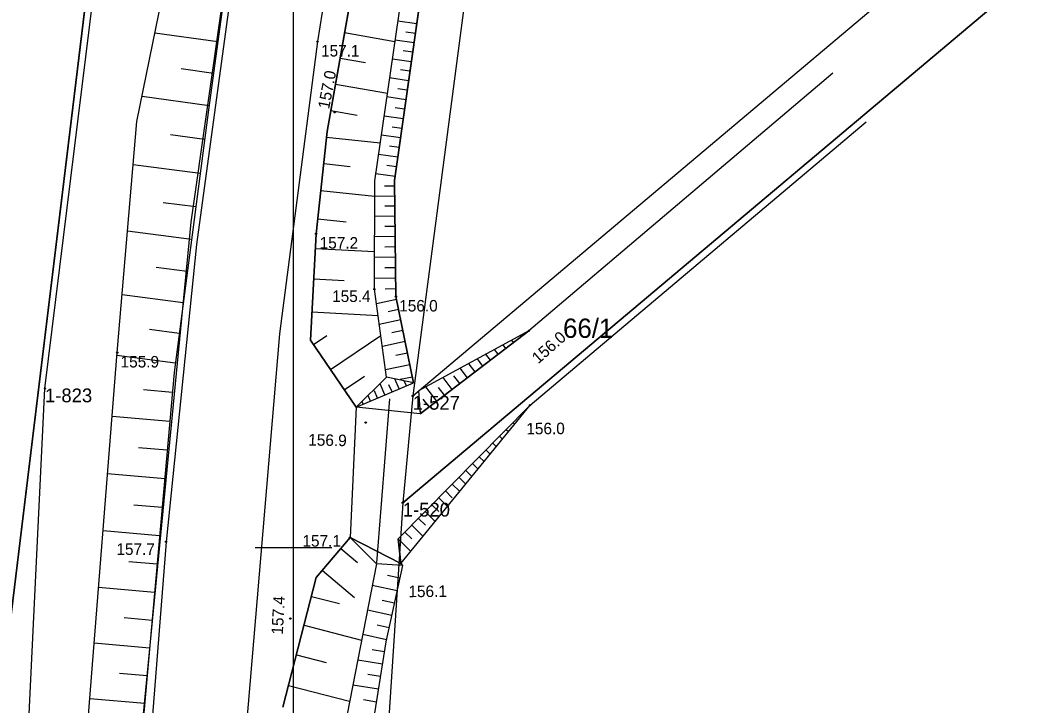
# Model space of a CAD drawing. Extents: x 5598798 to 5599616, y 5661498 to 5662453.
# Drawn here: x 5599182.2 to 5599247.3, y 5661939.7 to 5661984.4 of the extents above; entities that cross this region are included whole.
import ezdxf

# ---------------------------------------------------------------- set-up
doc = ezdxf.new("R2010")
doc.units = 0
for name, color, linetype in [('BUBZ_L_1', 7, 'Continuous'), ('BUIB_L_4', 7, 'Continuous'), ('Dzialki', 7, 'Continuous'), ('Kontury', 7, 'Continuous'), ('KTJZ_L_0', 7, 'Continuous'), ('Numery_dzialek', 7, 'Continuous'), ('Numery_punktow', 7, 'Continuous'), ('Podzial_sekcyjny_krzyze', 7, 'Continuous'), ('Podzial_sekcyjny_podstawowy', 7, 'Continuous'), ('PTRW_L_0', 7, 'Continuous'), ('Punkty', 7, 'Continuous'), ('RTPW_T_0', 7, 'Continuous'), ('SUPT_L_0', 7, 'Continuous'), ('SUPW_L_0', 7, 'Continuous'), ('Uzytki', 7, 'Continuous')]:
    doc.layers.add(name, color=color, linetype=linetype)

# ---------------------------------------------------------------- blocks, each defined once
blk = doc.blocks.new('GRO')
blk.add_circle((0, 0), 0.045)
blk = doc.blocks.new('POINT_DISPLAY')
blk.add_line((0, 0), (0, 0))
blk = doc.blocks.new('2_RTPW01')
blk.add_circle((0, 0), 0.045)

msp = doc.modelspace()

# ---------------------------------------------------------------- linework, layer by layer
at = {"layer": 'BUBZ_L_1'}
for p, q in [((5599189.8, 5661977.78), (5599196.49, 5662010.61)), ((5599198.63, 5662008.86), (5599194.46, 5661978.54)), ((5599205.3, 5661973.9), (5599209.49, 5662002.77)), ((5599206.61, 5662002.2), (5599202.2, 5661977.13)), ((5599210.61, 5662002.29), (5599206.59, 5661973.92)), ((5599208.037029, 5661984.131993), (5599206.810233, 5661984.305829)), ((5599203.333533, 5661983.573915), (5599206.620102, 5661982.995783)), ((5599207.950111, 5661983.518595), (5599207.335681, 5661983.605659)), ((5599195.067793, 5661982.959252), (5599190.970251, 5661983.522799)), ((5599207.863047, 5661982.904165), (5599206.632119, 5661983.078586)), ((5599207.775836, 5661982.288701), (5599207.159337, 5661982.376059)), ((5599203.040063, 5661981.905599), (5599204.708379, 5661981.61213)), ((5599207.688479, 5661981.672202), (5599206.453405, 5661981.84721)), ((5599194.786019, 5661980.910481), (5599192.671239, 5661981.201333)), ((5599207.600975, 5661981.054665), (5599206.982399, 5661981.142316)), ((5599207.513323, 5661980.436089), (5599206.27409, 5661980.611687)), ((5599202.742124, 5661980.21187), (5599206.129581, 5661979.615991)), ((5599207.425524, 5661979.816472), (5599206.804865, 5661979.904419)), ((5599194.495167, 5661978.7957), (5599190.129333, 5661979.396146)), ((5599207.337577, 5661979.195813), (5599206.09417, 5661979.372002)), ((5599194.46, 5661978.54), (5599192.22, 5661961.41)), ((5599202.439646, 5661978.492342), (5599204.159174, 5661978.189864)), ((5599207.249483, 5661978.574109), (5599206.626733, 5661978.662352)), ((5599188.51, 5661962.71), (5599189.8, 5661977.78)), ((5599207.16124, 5661977.95136), (5599205.913645, 5661978.128143)), ((5599202.2, 5661977.13), (5599201.48, 5661970.46)), ((5599207.072848, 5661977.327562), (5599206.448001, 5661977.416102)), ((5599194.207763, 5661976.611064), (5599191.978801, 5661976.902533)), ((5599202.159549, 5661976.755264), (5599205.659561, 5661976.377451)), ((5599206.984308, 5661976.702715), (5599205.732511, 5661976.880093)), ((5599206.895619, 5661976.076817), (5599206.268667, 5661976.165655)), ((5599206.80678, 5661975.449865), (5599205.550767, 5661975.627841)), ((5599193.916293, 5661974.382101), (5599189.557924, 5661974.952022)), ((5599201.974039, 5661975.036719), (5599203.692584, 5661974.851209)), ((5599206.717792, 5661974.821859), (5599206.088729, 5661974.910996)), ((5599205.28, 5661966.84), (5599205.3, 5661973.9)), ((5599206.628655, 5661974.192795), (5599205.368412, 5661974.371371)), ((5599206.59, 5661973.92), (5599206.68, 5661966.36)), ((5599201.784446, 5661973.280357), (5599205.29717, 5661972.901172)), ((5599206.594296, 5661973.55913), (5599205.946643, 5661973.55142)), ((5599206.602006, 5661972.911477), (5599205.297156, 5661972.895943)), ((5599193.631333, 5661972.202916), (5599191.500814, 5661972.481513)), ((5599206.609773, 5661972.259052), (5599205.95254, 5661972.251228)), ((5599201.58434, 5661971.426597), (5599203.4381, 5661971.226491)), ((5599206.617597, 5661971.601819), (5599205.293445, 5661971.586055)), ((5599193.352736, 5661970.072397), (5599189.186856, 5661970.617147)), ((5599206.625479, 5661970.939743), (5599205.958524, 5661970.931803)), ((5599201.48, 5661970.46), (5599201.11, 5661963.53)), ((5599206.633419, 5661970.272788), (5599205.289679, 5661970.256791)), ((5599201.428839, 5661969.501771), (5599205.286957, 5661969.295782)), ((5599206.641418, 5661969.600918), (5599205.964597, 5661969.59286)), ((5599206.649475, 5661968.924097), (5599205.285858, 5661968.907863)), ((5599193.080361, 5661967.989457), (5599191.043937, 5661968.25575)), ((5599206.657592, 5661968.242288), (5599205.970759, 5661968.234112)), ((5599201.323174, 5661967.52269), (5599203.302255, 5661967.417025)), ((5599206.665768, 5661967.555455), (5599205.28198, 5661967.538982)), ((5599206.08, 5661961.11), (5599205.28, 5661966.84)), ((5599206.674005, 5661966.863561), (5599205.977012, 5661966.855264)), ((5599192.814069, 5661965.953034), (5599188.832177, 5661966.473725)), ((5599206.719171, 5661966.170562), (5599205.411223, 5661965.900113)), ((5599206.68, 5661966.36), (5599207.84, 5661960.75)), ((5599201.208129, 5661965.36793), (5599205.517649, 5661965.137841)), ((5599206.854395, 5661965.516588), (5599206.179078, 5661965.376951)), ((5599206.994033, 5661964.841271), (5599205.599319, 5661964.552881)), ((5599192.553723, 5661963.962088), (5599190.607239, 5661964.216619)), ((5599207.138228, 5661964.143914), (5599206.418112, 5661963.995013)), ((5599215.350881, 5661964.125085), (5599208.146474, 5661960.209571)), ((5599208.270337, 5661958.721684), (5599215.350881, 5661964.125085)), ((5599201.11, 5661963.53), (5599204.09, 5661959.15)), ((5599201.308213, 5661963.238667), (5599202.171743, 5661963.826183)), ((5599202.423064, 5661961.60006), (5599205.700278, 5661963.829762)), ((5599207.287129, 5661963.423797), (5599205.799892, 5661963.116276)), ((5599214.350857, 5661963.361933), (5599214.232375, 5661963.51719)), ((5599214.850869, 5661963.743509), (5599214.791628, 5661963.821138)), ((5599213.350832, 5661962.598781), (5599213.113869, 5661962.909294)), ((5599213.850844, 5661962.980357), (5599213.673122, 5661963.213242)), ((5599186.4, 5661936.1), (5599188.51, 5661962.71)), ((5599192.299192, 5661962.015604), (5599188.49439, 5661962.513138)), ((5599207.44089, 5661962.680178), (5599206.673002, 5661962.521399)), ((5599212.350808, 5661961.835628), (5599211.995363, 5661962.301399)), ((5599212.85082, 5661962.217204), (5599212.554616, 5661962.605347)), ((5599207.599669, 5661961.91229), (5599206.013771, 5661961.584368)), ((5599211.350783, 5661961.072476), (5599210.876856, 5661961.693503)), ((5599211.850795, 5661961.454052), (5599211.469219, 5661961.954064)), ((5599192.22, 5661961.41), (5599190.05, 5661936.96)), ((5599203.317148, 5661960.285936), (5599204.631272, 5661961.180021)), ((5599204.09, 5661959.15), (5599206.08, 5661961.11)), ((5599207.84, 5661960.75), (5599206.08, 5661961.11)), ((5599206.900159, 5661960.349001), (5599206.622842, 5661960.998964)), ((5599207.76363, 5661961.119341), (5599206.955405, 5661960.952222)), ((5599207.37008, 5661960.549501), (5599207.231421, 5661960.874482)), ((5599210.350759, 5661960.309324), (5599209.75835, 5661961.085608)), ((5599210.850771, 5661960.6909), (5599210.469195, 5661961.190912)), ((5599192.104381, 5661960.107284), (5599190.217282, 5661960.274768)), ((5599204.09, 5661959.15), (5599207.84, 5661960.75)), ((5599205.490399, 5661959.747503), (5599205.289899, 5661960.217424)), ((5599205.960319, 5661959.948003), (5599205.646644, 5661960.683177)), ((5599206.430239, 5661960.148502), (5599206.22974, 5661960.618422)), ((5599208.146474, 5661960.209571), (5599208.270337, 5661958.721684)), ((5599209.350734, 5661959.546171), (5599208.639844, 5661960.477712)), ((5599209.850746, 5661959.927747), (5599209.46917, 5661960.42776)), ((5599204.550558, 5661959.346505), (5599204.473317, 5661959.527538)), ((5599205.020478, 5661959.547004), (5599204.864426, 5661959.912751)), ((5599208.850722, 5661959.164595), (5599208.469146, 5661959.664607)), ((5599215.430897, 5661959.284622), (5599206.834986, 5661950.565233)), ((5599207.011575, 5661948.958488), (5599215.430897, 5661959.284622)), ((5599208.35071, 5661958.783019), (5599208.254765, 5661958.908744)), ((5599215.196893, 5661959.047257), (5599215.21933, 5661959.025139)), ((5599191.936896, 5661958.220185), (5599188.180423, 5661958.553581)), ((5599214.756793, 5661958.600835), (5599214.821426, 5661958.537117)), ((5599213.876592, 5661957.70799), (5599214.025618, 5661957.561075)), ((5599214.316693, 5661958.154412), (5599214.423522, 5661958.049096)), ((5599213.436492, 5661957.261568), (5599213.627714, 5661957.073053)), ((5599191.770197, 5661956.341948), (5599189.900782, 5661956.507864)), ((5599212.556291, 5661956.368723), (5599212.831907, 5661956.097011)), ((5599212.996391, 5661956.815145), (5599213.22981, 5661956.585032)), ((5599212.116191, 5661955.922301), (5599212.434003, 5661955.60899)), ((5599211.23599, 5661955.029456), (5599211.638195, 5661954.632947)), ((5599211.67609, 5661955.475879), (5599212.036099, 5661955.120968)), ((5599191.604282, 5661954.472533), (5599187.883011, 5661954.802805)), ((5599210.79589, 5661954.583034), (5599211.240291, 5661954.144926)), ((5599209.915689, 5661953.690189), (5599210.362111, 5661953.250089)), ((5599210.355789, 5661954.136612), (5599210.842387, 5661953.656904)), ((5599209.475588, 5661953.243767), (5599210.04658, 5661952.680862)), ((5599191.439146, 5661952.611897), (5599189.587249, 5661952.776258)), ((5599208.595388, 5661952.350922), (5599209.250772, 5661951.704819)), ((5599209.035488, 5661952.797345), (5599209.48191, 5661952.357244)), ((5599208.155287, 5661951.9045), (5599208.60171, 5661951.4644)), ((5599191.274785, 5661950.76), (5599187.588386, 5661951.087178)), ((5599207.715187, 5661951.458078), (5599208.454964, 5661950.728777)), ((5599201.49, 5661948.04), (5599203.69, 5661950.65)), ((5599203.69, 5661950.65), (5599205.42, 5661948.94)), ((5599206.834986, 5661950.565233), (5599207.011575, 5661948.958488)), ((5599206.834986, 5661950.565233), (5599207.659157, 5661949.752734)), ((5599207.275086, 5661951.011655), (5599207.721509, 5661950.571555)), ((5599203.096379, 5661949.945749), (5599204.178034, 5661949.034009)), ((5599191.111197, 5661948.916801), (5599189.276653, 5661949.079621)), ((5599201.891058, 5661948.515801), (5599203.981475, 5661946.753763)), ((5599205.42, 5661948.94), (5599203.24, 5661937.82)), ((5599207.13, 5661948.83), (5599205.42, 5661948.94)), ((5599206.04, 5661943.86), (5599207.13, 5661948.83)), ((5599199.31, 5661939.6), (5599201.49, 5661948.04)), ((5599206.948566, 5661948.002729), (5599206.127704, 5661948.182757)), ((5599190.948376, 5661947.082257), (5599187.296522, 5661947.406369)), ((5599206.768538, 5661947.181866), (5599205.145129, 5661947.537906)), ((5599201.174892, 5661946.820039), (5599202.99736, 5661946.349307)), ((5599206.590518, 5661946.370162), (5599205.78787, 5661946.546195)), ((5599206.414485, 5661945.567513), (5599204.827097, 5661945.915652)), ((5599190.786321, 5661945.25633), (5599188.968969, 5661945.417625)), ((5599200.689788, 5661944.941931), (5599204.446003, 5661943.971724)), ((5599206.240415, 5661944.773819), (5599205.455576, 5661944.945947)), ((5599206.068288, 5661943.988981), (5599204.516122, 5661944.329395)), ((5599190.625026, 5661943.438978), (5599187.007393, 5661943.760052)), ((5599205.05, 5661937.6), (5599206.04, 5661943.86)), ((5599205.936517, 5661943.20565), (5599205.140837, 5661943.331485)), ((5599200.189874, 5661943.006485), (5599202.12532, 5661942.506572)), ((5599205.810682, 5661942.409971), (5599204.190077, 5661942.666265)), ((5599190.464489, 5661941.630162), (5599188.664167, 5661941.789945)), ((5599205.682535, 5661941.599668), (5599204.857341, 5661941.73017)), ((5599199.674698, 5661941.011951), (5599203.663767, 5661939.981599)), ((5599205.552033, 5661940.774474), (5599203.871313, 5661941.040275)), ((5599190.304706, 5661939.82984), (5599186.720973, 5661940.147905)), ((5599205.419133, 5661939.934114), (5599204.563328, 5661940.069456))]:
    msp.add_line(p, q, dxfattribs=at)
at = {"layer": 'BUIB_L_4'}
msp.add_line((5599205.439605, 5661949.012802), (5599206.277475, 5661959.686865), dxfattribs=at)
at = {"layer": 'Dzialki'}
for p, q in [((5599207.78, 5661959.89), (5599289.91, 5662029.05)), ((5599207.13, 5661952.92), (5599291.05, 5662023.52)), ((5599212.74, 5661997.6), (5599207.78, 5661959.89)), ((5599183.8, 5661960.37), (5599187.02, 5661986.57)), ((5599182.1, 5661925.2), (5599183.8, 5661960.37)), ((5599207.78, 5661959.89), (5599207.13, 5661952.92)), ((5599207.13, 5661952.92), (5599202.8, 5661886.51))]:
    msp.add_line(p, q, dxfattribs=at)
at = {"layer": 'Kontury'}
for p, q in [((5599207.78, 5661959.89), (5599289.91, 5662029.05)), ((5599291.05, 5662023.52), (5599207.13, 5661952.92)), ((5599212.74, 5661997.6), (5599207.78, 5661959.89)), ((5599183.8, 5661960.37), (5599187.02, 5661986.57)), ((5599182.1, 5661925.2), (5599183.8, 5661960.37)), ((5599207.13, 5661952.92), (5599202.8, 5661886.51))]:
    msp.add_line(p, q, dxfattribs=at)
at = {"layer": 'KTJZ_L_0'}
for p, q in [((5599204.57, 5662002.13), (5599201.57, 5661982.98)), ((5599202.2, 5661977.13), (5599206.61, 5662002.2)), ((5599196.27, 5661988.82), (5599193.67, 5661969.75)), ((5599201.57, 5661982.98), (5599199.1, 5661963.93)), ((5599235.17, 5661980.92), (5599215.35, 5661964.13)), ((5599215.43, 5661959.28), (5599237.35, 5661977.76)), ((5599201.48, 5661970.46), (5599202.2, 5661977.13)), ((5599201.11, 5661963.53), (5599201.48, 5661970.46)), ((5599193.67, 5661969.75), (5599191.7, 5661950.38)), ((5599215.35, 5661964.13), (5599208.27, 5661958.72)), ((5599199.1, 5661963.93), (5599196.72, 5661936.01)), ((5599204.09, 5661959.15), (5599201.11, 5661963.53)), ((5599204.09, 5661959.15), (5599203.69, 5661950.65)), ((5599208.27, 5661958.72), (5599204.09, 5661959.15)), ((5599206.83, 5661950.57), (5599215.43, 5661959.28)), ((5599191.7, 5661950.38), (5599190.16, 5661930.69)), ((5599201.49, 5661948.04), (5599203.69, 5661950.65)), ((5599203.69, 5661950.65), (5599207.01, 5661948.96)), ((5599207.01, 5661948.96), (5599206.83, 5661950.57)), ((5599199.31, 5661939.6), (5599201.49, 5661948.04))]:
    msp.add_line(p, q, dxfattribs=at)
at = {"layer": 'Podzial_sekcyjny_krzyze'}
for p, q in [((5599200, 5661947.5), (5599200, 5661952.5)), ((5599197.5, 5661950), (5599202.5, 5661950))]:
    msp.add_line(p, q, dxfattribs=at)
at = {"layer": 'Podzial_sekcyjny_podstawowy'}
msp.add_line((5599200, 5661750), (5599200, 5662000), dxfattribs=at)
at = {"layer": 'PTRW_L_0'}
for p, q in [((5599206.61, 5662002.2), (5599202.2, 5661977.13)), ((5599206.59, 5661973.92), (5599210.61, 5662002.29)), ((5599202.2, 5661977.13), (5599201.48, 5661970.46)), ((5599206.68, 5661966.36), (5599206.59, 5661973.92)), ((5599201.48, 5661970.46), (5599201.11, 5661963.53)), ((5599207.84, 5661960.75), (5599206.68, 5661966.36)), ((5599201.11, 5661963.53), (5599204.09, 5661959.15)), ((5599204.09, 5661959.15), (5599207.84, 5661960.75)), ((5599203.69, 5661950.65), (5599201.49, 5661948.04)), ((5599207.01, 5661948.96), (5599203.69, 5661950.65)), ((5599206.04, 5661943.86), (5599207.13, 5661948.83)), ((5599207.13, 5661948.83), (5599207.01, 5661948.96)), ((5599201.49, 5661948.04), (5599199.31, 5661939.6)), ((5599205.05, 5661937.6), (5599206.04, 5661943.86))]:
    msp.add_line(p, q, dxfattribs=at)
at = {"layer": 'SUPT_L_0'}
for p, q in [((5599196.624161, 5661994.403918), (5599193.309647, 5661971.20769)), ((5599193.309647, 5661971.20769), (5599189.54249, 5661932.273767))]:
    msp.add_line(p, q, dxfattribs=at)
at = {"layer": 'SUPW_L_0'}
for p, q in [((5599181.036243, 5661940.982154), (5599189.084637, 5662007.286789)), ((5599189.084637, 5662007.286789), (5599181.036243, 5661940.982154))]:
    msp.add_line(p, q, dxfattribs=at)
at = {"layer": 'Uzytki'}
for p, q in [((5599207.78, 5661959.89), (5599289.91, 5662029.05)), ((5599291.05, 5662023.52), (5599207.13, 5661952.92)), ((5599212.74, 5661997.6), (5599207.78, 5661959.89)), ((5599183.8, 5661960.37), (5599187.02, 5661986.57)), ((5599182.1, 5661925.2), (5599183.8, 5661960.37)), ((5599207.13, 5661952.92), (5599202.8, 5661886.51))]:
    msp.add_line(p, q, dxfattribs=at)

# ---------------------------------------------------------------- block references
at = {"layer": 'BUBZ_L_1'}
for p in [(5599215.350881, 5661964.125085), (5599207.84, 5661960.75), (5599204.09, 5661959.15), (5599207.13, 5661948.83)]:
    msp.add_blockref('POINT_DISPLAY', p, dxfattribs=at)
at = {"layer": 'Punkty'}
for p in [(5599183.8, 5661960.37), (5599207.78, 5661959.89), (5599207.13, 5661952.92)]:
    msp.add_blockref('GRO', p, dxfattribs=at)
at = {"layer": 'RTPW_T_0', "rotation": -3.0000000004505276e-06}
for p in [(5599201.57, 5661982.98), (5599201.48, 5661970.46), (5599205.28, 5661966.84), (5599206.68, 5661966.36), (5599188.51, 5661962.71), (5599191.7, 5661950.38), (5599203.69, 5661950.65)]:
    msp.add_blockref('2_RTPW01', p, dxfattribs=at)
at = {"layer": 'RTPW_T_0'}
for p in [(5599202.691207, 5661978.374197), (5599215.350881, 5661964.125085), (5599215.430897, 5661959.284622), (5599204.711648, 5661958.150569), (5599207.011575, 5661948.958488), (5599199.799666, 5661945.372959)]:
    msp.add_blockref('2_RTPW01', p, dxfattribs=at)

# ---------------------------------------------------------------- texts
at = {"layer": 'Numery_dzialek'}
msp.add_text('66/1', height=1.26, dxfattribs=at).set_placement((5599217.583024, 5661963.669568))
at = {"layer": 'Numery_punktow'}
for s, p in [('1-823', (5599183.8, 5661959.47)), ('1-527', (5599207.78, 5661958.99)), ('1-520', (5599207.13, 5661952.02))]:
    msp.add_text(s, height=0.9, dxfattribs=at).set_placement(p)
at = {"layer": 'RTPW_T_0'}
for s, p in [('157.1', (5599201.8, 5661982.01)), ('157.2', (5599201.71, 5661969.49)), ('155.4', (5599202.52273, 5661966.008924)), ('156.0', (5599206.9, 5661965.39)), ('155.9', (5599188.73, 5661961.74)), ('157.1', (5599200.587425, 5661950.062866)), ('157.7', (5599188.457266, 5661949.523049))]:
    msp.add_text(s, height=0.75, dxfattribs=at).set_placement(p)
for s, rotation, p in [('157.0', 79.143578, (5599202.325349, 5661978.549208)), ('156.0', 41.227722, (5599215.958559, 5661961.943843)), ('156.0', 0.496053, (5599215.189896, 5661957.375901)), ('156.9', 358.939088, (5599200.960789, 5661956.654332)), ('156.1', 0.530504, (5599207.50024, 5661946.765782)), ('157.4', 86.869751, (5599199.308292, 5661944.313415))]:
    msp.add_text(s, height=0.75, rotation=rotation, dxfattribs=at).set_placement(p)

doc.saveas('drawing.dxf')
